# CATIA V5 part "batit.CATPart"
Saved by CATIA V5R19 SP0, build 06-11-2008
Part number: skl_batit
Publications: "axe_pivot_batit_roue1", "axe_pivot_batit_sabot1", "axe_pivot_batit_levier", "axe_pivot_batit_sabot2", "axe_pivot_batit_roue2", "Plan.10", "Plan.13", "Plan.14"
Bounding box of the stored display mesh (mm): x -500 to 500, y 270 to 560, z -20 to 20
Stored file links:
  C:\Users\Thibaud\Desktop\IFMA\thinkmotion\IAO\modele_catia\squelette\batit.CATPart
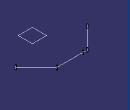
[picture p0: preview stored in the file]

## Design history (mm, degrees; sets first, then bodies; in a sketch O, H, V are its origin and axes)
Body1 (main body)
  Point1: stored without definition
  Point2: stored without definition
  Line1: type PtPt, SecondPoint Point2, FirstPoint Point1
  Point3: stored without definition
  Point4 "Point.12": stored without definition
  Line2: type PtPt, SecondPoint Point4, FirstPoint Point3
  Point5 "Point.12": stored without definition
  Point6: stored without definition
  Line3: type PtPt, SecondPoint Point6, FirstPoint Point5
  Point7: stored without definition
  Point8: stored without definition
  Line4: type PtPt, SecondPoint Point8, FirstPoint Point7
  Plane1: stored without definition
  Point9: stored without definition
  Line5 "axe_pivot_batit_roue1": type Normal, RefSkin Plane1, Start -20, End 20, RefPoint Point9
  Plane2: stored without definition
  Point10: stored without definition
  Line6 "axe_pivot_batit_sabot1": type Normal, RefSkin Plane2, Start -20, End 20, RefPoint Point10
  Plane3: stored without definition
  Point11 "Point.12": stored without definition
  Line7 "axe_pivot_batit_levier": type Normal, RefSkin Plane3, Start -20, End 20, RefPoint Point11
  Plane4: stored without definition
  Point12: stored without definition
  Line8 "axe_pivot_batit_sabot2": type Normal, RefSkin Plane4, Start -20, End 20, RefPoint Point12
  Plane5: stored without definition
  Point13: stored without definition
  Line9 "axe_pivot_batit_roue2": type Normal, RefSkin Plane5, Start -20, End 20, RefPoint Point13
  Point14: stored without definition
  Plane6: type Offset, Offset 50, RefPlane xy-plane, reversed
  Plane7: type Offset, Offset 15, RefPlane Plane3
